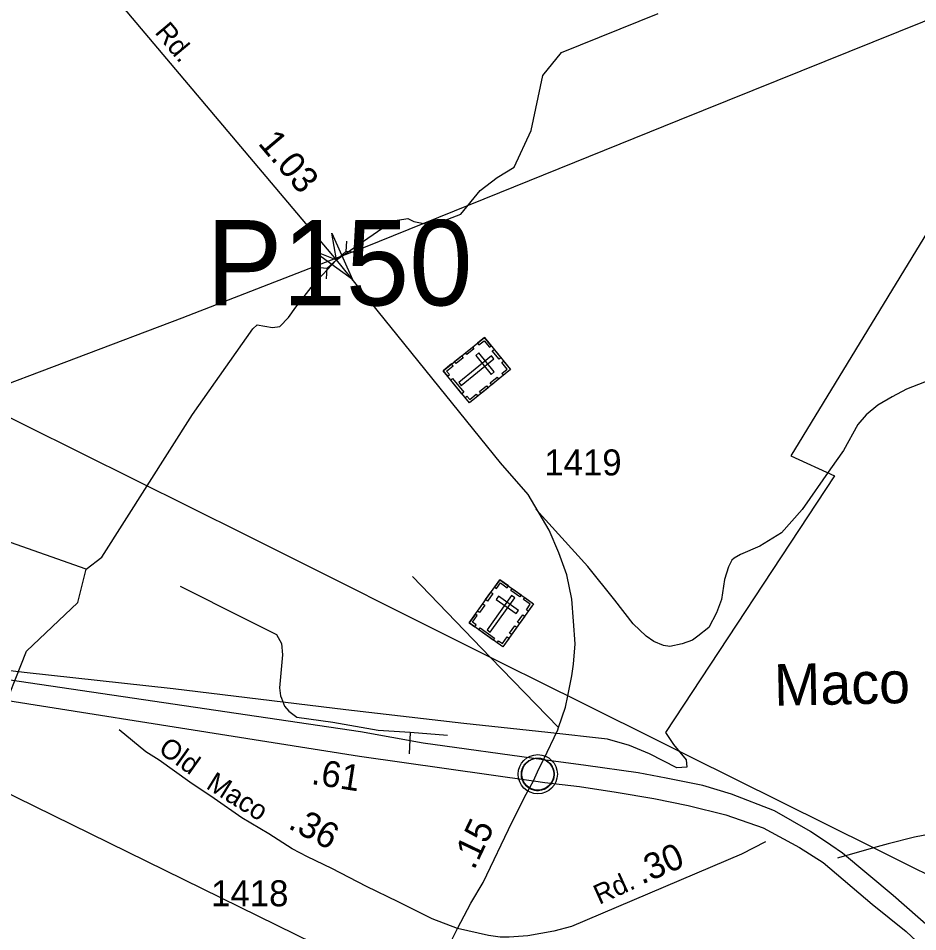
# Model space of a CAD drawing. Extents: x 2225501 to 2309677, y 165449 to 227696.
# Drawn here: x 2257649 to 2261977, y 195485 to 199877 of the extents above; entities that cross this region are included whole.
import ezdxf

# ---------------------------------------------------------------- set-up
doc = ezdxf.new("R2010")
doc.units = 0
for name, color, linetype in [('Black Area Fill Shapes', 7, 'Continuous'), ('E_RDY_CMT_EOP', 7, 'Continuous'), ('ENG SEALS CELL', 7, 'Continuous'), ('MARK ENDS WORD SYMBOL CELL', 7, 'Continuous'), ('Old_Level_3', 7, 'Continuous'), ('Old_Level_33', 7, 'Continuous'), ('Old_Level_44', 7, 'Continuous'), ('Old_Level_46', 7, 'Continuous'), ('Old_Level_50', 7, 'Continuous'), ('Old_Level_52', 7, 'Continuous'), ('P_HYD_Diversion_Ditch_Label', 7, 'Continuous'), ('P_HYD_Drop_Inlet_Grate_3_Narrow_Slot_and_Sag_Grates_840_22_Type_A_60_Dia-Top_CELL', 7, 'Continuous'), ('P_HYD_Endwall_838_01_48_Dia_Single_CELL', 7, 'Continuous'), ('P_HYD_RipRap_Pad_876_02_36in_Outlet_With_Ditch-Top_CELL', 7, 'Continuous'), ('P_RDY_Dimension_Text', 7, 'Continuous'), ('Prop Mkg Solid Yellow Edge Line', 7, 'Continuous'), ('Prop Support', 7, 'Continuous'), ('Raster_Level_0', 7, 'Continuous'), ('Scratch_Level_4', 7, 'Continuous'), ('Typical Terminator CELL', 7, 'Continuous')]:
    doc.layers.add(name, color=color, linetype=linetype)

msp = doc.modelspace()

# ---------------------------------------------------------------- linework, layer by layer
at = {"layer": 'Black Area Fill Shapes'}
for p, q in [((2260818.3, 196358.1), (2260293.7, 196618.7)), ((2260878.5, 196328.2), (2260818.3, 196358.1)), ((2261764.5, 195887.9), (2260878.5, 196328.2))]:
    msp.add_line(p, q, dxfattribs=at)
for points in [[(2262843.4, 200184.7), (2262114.8, 199904.5), (2260829.4, 199388.1), (2259311, 198774), (2259154.8, 198713.5)], [(2259154.8, 198713.5), (2258436.2, 198435), (2257417.6, 198050.9)], [(2259922.2, 196804.3), (2258742.4, 197393.8), (2257417.6, 198050.9)], [(2260293.7, 196618.7), (2260237.9, 196646.5), (2259922.2, 196804.3)], [(2264419.4, 194543.5), (2262221.2, 195661.1), (2261764.5, 195887.9)]]:
    msp.add_lwpolyline(points, dxfattribs=at)
at = {"layer": 'ENG SEALS CELL'}
msp.add_lwpolyline([(2259158.2, 198843.7), (2259257.2, 198620.8), (2259060.1, 198764.3), (2259180.6, 198715.6)], close=True, dxfattribs=at)
at = {"layer": 'Old_Level_3'}
for p, q in [((2259922.2, 196804.3), (2259545.7, 197192.6)), ((2260249.4, 196466.7), (2259922.2, 196804.3)), ((2259535.6, 196444.5), (2259533.7, 196408.1)), ((2259535.6, 196444.5), (2259714.6, 196430)), ((2259533.7, 196408.1), (2259530.1, 196340.4)), ((2259308.7, 195312.8), (2257312.8, 196291)), ((2261669.9, 195861.5), (2261600, 195841.9)), ((2261764.5, 195887.9), (2261669.9, 195861.5)), ((2261600, 195841.9), (2261591, 195839.4))]:
    msp.add_line(p, q, dxfattribs=at)
for points in [[(2263428.3, 199760.2), (2263330.4, 199632.5), (2263077.1, 199318.5), (2262950.9, 199099.6), (2262856, 198960.9), (2262781.6, 198776.4), (2262724.3, 198690), (2262583.6, 198528.9), (2262379.3, 198345.4), (2262276, 198256.4), (2262075, 198152.9), (2261923.5, 198093.7), (2261853.8, 198057.1), (2261784.2, 198016.6), (2261728.5, 197970.1), (2261689, 197923.7), (2261620, 197799.3), (2261557.7, 197710.9)], [(2261557.7, 197710.9), (2261420.3, 197515.8), (2261321.4, 197403), (2261217.9, 197338.2), (2261124.4, 197299.5), (2261094.4, 197281.2), (2261082.4, 197271.1), (2261066.8, 197239), (2261047.3, 197178.8), (2261032.2, 197082.7), (2261008.5, 197018.6), (2260971.2, 196948.3), (2260919.6, 196905.9), (2260893.8, 196887.6), (2260843.9, 196869.2), (2260784, 196856.8), (2260753.9, 196860.6), (2260707.9, 196880.3), (2260669.6, 196905.8), (2260607.2, 196965.4), (2260520.4, 197078.7), (2260389, 197241.4), (2260138.9, 197517.2)], [(2258428.2, 197146), (2258737.7, 196991.2), (2258892.4, 196913.8), (2258916.6, 196870.3), (2258921.5, 196817), (2258911.8, 196710.6), (2258906.9, 196657.4), (2258911.8, 196618.7), (2258915.9, 196608.3)], [(2264213.9, 196708.8), (2264138.5, 196626.3), (2264122.6, 196618.2), (2264068.8, 196599.8), (2264032.8, 196599.5), (2263983, 196589.1), (2263955, 196588.9), (2263893.1, 196580.3), (2263837.3, 196552), (2263785.6, 196511.4), (2263350.9, 196124.1), (2263301.3, 196089.7), (2263277.4, 196067.6), (2263231.7, 196037.1), (2263199.9, 196020.9), (2263098, 196002.1), (2262894.3, 195982.5), (2262476.4, 195985), (2262344.6, 195990), (2262174.7, 195976.5), (2262044.9, 195955.4), (2261961, 195938.9), (2261835.3, 195907.7), (2261764.5, 195887.9)], [(2258915.9, 196608.3), (2258931.1, 196570.3), (2258950.5, 196546.1), (2258989.2, 196517.1), (2259163.3, 196492.9), (2259380.9, 196454.2), (2259535.6, 196444.5)]]:
    msp.add_lwpolyline(points, dxfattribs=at)
at = {"layer": 'Old_Level_33'}
for points in [[(2260176.7, 196311.4), (2260245.5, 196456.5), (2260249.4, 196466.7), (2260282.7, 196564.8), (2260293.7, 196618.7), (2260313.4, 196715), (2260320.9, 196771), (2260328.2, 196869.1), (2260321.1, 196979), (2260313.2, 197083.4), (2260289.4, 197200.9), (2260250.2, 197306.6), (2260204.2, 197415.6), (2260102.1, 197587.7), (2259969.3, 197739.9), (2259180.6, 198715.6), (2257441.8, 200774), (2257406.3, 200835.2)], [(2259763.1, 195500.3), (2259640.9, 195547.4), (2259476.5, 195629.2), (2259324.2, 195701.9), (2259157.5, 195788.6), (2259040.4, 195845), (2258967.9, 195884.1), (2258854.3, 195956), (2258725.6, 196032.9), (2258592.8, 196125.9), (2258474.4, 196204.8), (2258327.5, 196309.6), (2258262.5, 196349.9), (2258134.9, 196456.2)], [(2261244.4, 195917), (2261128.6, 195857.3), (2260311.7, 195510.7), (2260226.7, 195487.1), (2260101.7, 195465.8), (2260011.4, 195458.2), (2259967.8, 195458.6), (2259911.7, 195466.3), (2259763.1, 195500.3)]]:
    msp.add_lwpolyline(points, dxfattribs=at)
at = {"layer": 'Old_Level_44'}
for p, q in [((2259228.2, 198806.1), (2259226.1, 198755.4)), ((2259135, 198675.9), (2259226.1, 198755.4)), ((2259276.7, 198750.6), (2259226.1, 198755.4)), ((2259084.5, 198680.7), (2259135, 198675.9)), ((2259133, 198625.1), (2259135, 198675.9))]:
    msp.add_line(p, q, dxfattribs=at)
at = {"layer": 'Old_Level_46'}
for points in [[(2260176.7, 196311.4), (2259597.7, 196392.1), (2259295.9, 196446.1), (2256956.7, 196790)], [(2256960.1, 196697.4), (2259291.8, 196328.6), (2260129, 196210.1)], [(2264217.6, 193561.9), (2264055, 193704.6), (2263946.8, 193788.4), (2263787.2, 193926.8), (2263500, 194184.9), (2263249.2, 194403.1), (2263105.6, 194549.5), (2262415.7, 195153.5), (2262043.4, 195496.8), (2261859.5, 195658.7), (2261615.3, 195862.4), (2261558.7, 195901.5), (2261461.5, 195966.3), (2261288.3, 196066.6), (2261080.3, 196146.7), (2260942.6, 196188.6), (2260766.4, 196223.2), (2260631.5, 196248.5), (2260380.2, 196284.4), (2260176.7, 196311.4)], [(2260129, 196210.1), (2260182.5, 196202.5), (2260349.2, 196183.2), (2260525.3, 196155.2), (2260707.8, 196126.2), (2260872.5, 196091.5), (2261053.4, 196046.8), (2261232.8, 195983.9), (2261407.6, 195889.4), (2261522.3, 195817.9), (2261757.7, 195618.2), (2261921.5, 195486), (2262216.4, 195210.8), (2262990.7, 194529), (2263196.2, 194348.8), (2263442, 194122.8), (2263721, 193886.9), (2263872.7, 193751), (2263970.5, 193659.8), (2264144.9, 193502.9)]]:
    msp.add_lwpolyline(points, dxfattribs=at)
at = {"layer": 'Old_Level_50'}
for points in [[(2260129, 196210.1), (2260154.7, 196268.2), (2260176.7, 196311.4)], [(2259763.1, 195500.3), (2259826.1, 195622.5), (2259886.6, 195722.2), (2260025.5, 196013.6), (2260093.6, 196146.1), (2260129, 196210.1)], [(2258595.8, 192338.5), (2258629.6, 192532.4), (2258664.3, 192655.9), (2258691.3, 192729.2), (2258737.6, 192818.2), (2258791.6, 192928.2), (2258843.7, 193034.3), (2258916, 193180), (2258987.4, 193322.8), (2259027.9, 193421.3), (2259081.9, 193556.3), (2259101.2, 193637.4), (2259145.6, 193859.3), (2259184.1, 194038.8), (2259210.2, 194167.1), (2259233.7, 194275.2), (2259281.8, 194509.4), (2259328.8, 194619.8), (2259446.5, 194872.8), (2259510.1, 195004.1), (2259562.2, 195102.5), (2259660.6, 195295.4), (2259763.1, 195500.3)]]:
    msp.add_lwpolyline(points, dxfattribs=at)
at = {"layer": 'P_HYD_Diversion_Ditch_Label'}
msp.add_lwpolyline([(2260071.4, 196254.6), (2260072.4, 196260.2), (2260074.2, 196266.8), (2260077.1, 196274), (2260080, 196279.7), (2260083.4, 196285.4), (2260087.1, 196290.6), (2260091.1, 196294.9), (2260095.7, 196299.5), (2260101.2, 196304.1), (2260106.6, 196307.8), (2260111.5, 196310.6), (2260116.6, 196313.1), (2260122, 196315.4), (2260127.7, 196317.2), (2260132, 196318.4), (2260136.8, 196319.1), (2260141, 196319.8), (2260147.3, 196320.1), (2260151.8, 196320), (2260157.4, 196319.7), (2260162.3, 196319), (2260167.2, 196318), (2260172.2, 196316.6), (2260177.4, 196314.7), (2260184.1, 196311.7), (2260190.3, 196308.2), (2260195.4, 196304.7), (2260200.5, 196300.7), (2260203.9, 196297.5), (2260208, 196293.2), (2260211.8, 196288.5), (2260214.9, 196283.9), (2260218.1, 196278.9), (2260220.5, 196273.7), (2260222.5, 196268.7), (2260224.1, 196263.7), (2260225.4, 196259.1), (2260226.5, 196253), (2260227.1, 196248.3), (2260227.4, 196242.3), (2260227.2, 196236.5), (2260226.6, 196230.9), (2260225.7, 196225.4), (2260224, 196219.2), (2260222.1, 196213.4), (2260219.9, 196208.3), (2260216.7, 196202.3), (2260213.4, 196197), (2260210, 196192.3), (2260205.7, 196187.6), (2260200.4, 196182.6), (2260195.4, 196178.5), (2260190.4, 196175), (2260186.1, 196172.5), (2260179.3, 196169.3), (2260172.1, 196166.6), (2260166.2, 196165.1), (2260159.6, 196163.8), (2260155.1, 196163.3), (2260150.7, 196163.1), (2260145.1, 196163.1), (2260140.8, 196163.5), (2260135.2, 196164.2), (2260129.2, 196165.5), (2260124.7, 196166.8), (2260119.5, 196168.7), (2260114.9, 196170.7), (2260111, 196172.9), (2260104.2, 196177), (2260098.6, 196181.3), (2260093.7, 196185.8), (2260089.2, 196190.6), (2260086, 196194.6), (2260083.1, 196198.8), (2260079, 196205.9), (2260077.2, 196209.4), (2260075.5, 196213.4), (2260072.9, 196221.6), (2260071.4, 196228.7), (2260070.7, 196233.8), (2260070.4, 196240.2), (2260070.3, 196244.8), (2260070.9, 196251.3)], close=True, dxfattribs=at)
for centre, radius in [((2260149, 196242.2), 94.3), ((2260148.7, 196242.5), 76.7)]:
    msp.add_circle(centre, radius, dxfattribs=at)
at = {"layer": 'P_HYD_Endwall_838_01_48_Dia_Single_CELL'}
msp.add_lwpolyline([(2262842.5, 200192.5), (2261366.2, 197772.7), (2261577, 197677.7), (2260763, 196442.2), (2260802.2, 196384.7), (2260862.2, 196311.2), (2260865.8, 196276.6), (2260817.5, 196273.6), (2260687.2, 196340.6), (2260589.5, 196380.7), (2260484.8, 196410.3), (2260197, 196442.9), (2259793.2, 196485.6), (2259224.8, 196551.9), (2258394, 196652.1), (2257678.2, 196731.8), (2257280, 196779.1), (2256995.8, 196809.4), (2256790.2, 196891.6), (2256494.5, 197038.7)], dxfattribs=at)
at = {"layer": 'P_HYD_RipRap_Pad_876_02_36in_Outlet_With_Ditch-Top_CELL'}
msp.add_lwpolyline([(2262842.5, 200192.5), (2261366.2, 197772.7), (2261577, 197677.7), (2260763, 196442.2), (2260802.2, 196384.7), (2260862.2, 196311.2), (2260865.8, 196276.6), (2260817.5, 196273.6), (2260687.2, 196340.6), (2260589.5, 196380.7), (2260484.8, 196410.3), (2260197, 196442.9), (2259793.2, 196485.6), (2259224.8, 196551.9), (2258394, 196652.1), (2257678.2, 196731.8), (2257280, 196779.1), (2256995.8, 196809.4), (2256790.2, 196891.6), (2256494.5, 197038.7)], dxfattribs=at)
at = {"layer": 'Prop Mkg Solid Yellow Edge Line'}
for points in [[(2259891.9, 198342.8), (2260017.4, 198188.3), (2259819.8, 198027.7), (2259694.3, 198182.3)], [(2259858.3, 198315.5), (2259865.4, 198306.7), (2259890.4, 198327), (2259916, 198295.5), (2259924.6, 198302.5), (2259891.9, 198342.8)], [(2259800.7, 198268.8), (2259834.3, 198296.1), (2259841.5, 198287.2), (2259807.9, 198259.9)], [(2259938.6, 198285.3), (2259971.3, 198245.1), (2259962.4, 198237.9), (2259929.7, 198278.1)], [(2259748.5, 198226.4), (2259782.1, 198253.7), (2259789.3, 198244.9), (2259755.7, 198217.6)], [(2259937.9, 198239.7), (2259926.1, 198254.2), (2259768.7, 198126.4), (2259780.5, 198111.9)], [(2259864.8, 198268.2), (2259850.3, 198256.4), (2259924.5, 198165.1), (2259939, 198176.8)], [(2259715.1, 198156.6), (2259724.1, 198163.9), (2259710.2, 198180.9), (2259741.6, 198206.4), (2259734.5, 198215.1), (2259694.3, 198182.3)], [(2259983.8, 198160.9), (2259976.6, 198169.7), (2260001.6, 198190), (2259976.1, 198221.5), (2259984.7, 198228.5), (2260017.4, 198188.2)], [(2259739.4, 198144.9), (2259792.9, 198079), (2259784, 198071.9), (2259730.5, 198137.7)], [(2259919.9, 198123.7), (2259953.5, 198151), (2259960.7, 198142.1), (2259927.1, 198114.8)], [(2259868.7, 198082.1), (2259902.3, 198109.4), (2259909.5, 198100.6), (2259875.9, 198073.3)], [(2259798.9, 198053.5), (2259807.8, 198060.7), (2259821.7, 198043.6), (2259853, 198069.1), (2259860.1, 198060.5), (2259819.8, 198027.7)], [(2259966, 197177.6), (2260128.4, 197062.3), (2259981, 196854.7), (2259818.7, 196969.9)], [(2259941, 197142.2), (2259950.2, 197135.7), (2259968.8, 197161.9), (2260001.9, 197138.4), (2260008.4, 197147.5), (2259966, 197177.6)], [(2260026.4, 197134.7), (2260068.7, 197104.7), (2260062.1, 197095.4), (2260019.8, 197125.4)], [(2259898, 197081.8), (2259923.1, 197117.1), (2259932.4, 197110.5), (2259907.3, 197075.2)], [(2260038, 197090.6), (2260022.7, 197101.4), (2259905.4, 196936), (2259920.6, 196925.2)], [(2259959.9, 197098.4), (2259949.1, 197083.2), (2260045.1, 197015.1), (2260055.9, 197030.3)], [(2260103.3, 197026.9), (2260094.1, 197033.5), (2260112.7, 197059.7), (2260079.6, 197083.2), (2260086.1, 197092.3), (2260128.4, 197062.3)], [(2259859.1, 197027), (2259884.2, 197062.3), (2259893.5, 197055.7), (2259868.4, 197020.4)], [(2259845.7, 196950.8), (2259852.3, 196960.2), (2259834.4, 196972.9), (2259857.8, 197005.9), (2259848.7, 197012.3), (2259818.6, 196970)], [(2260051.7, 196973.9), (2260076.8, 197009.3), (2260086.1, 197002.7), (2260061, 196967.4)], [(2259872.2, 196946), (2259941.4, 196896.9), (2259934.8, 196887.6), (2259865.6, 196936.7)], [(2260013.6, 196920.2), (2260038.6, 196955.5), (2260047.9, 196948.9), (2260022.8, 196913.6)], [(2259954, 196873.9), (2259960.6, 196883.2), (2259978.6, 196870.5), (2260002, 196903.5), (2260011, 196897), (2259981, 196854.7)]]:
    msp.add_lwpolyline(points, close=True, dxfattribs=at)
at = {"layer": 'Prop Support'}
msp.add_lwpolyline([(2257976.7, 197228), (2257584.7, 197366.8), (2257283.7, 197431.8), (2256982.6, 197562.3), (2256580.7, 197793.2), (2256244.7, 198222.8), (2256076.7, 198360.5), (2255901.6, 198426.3), (2255659.7, 198424.5), (2255501.8, 198375), (2255013.7, 198004.1), (2254579.6, 198042), (2254396.7, 198006.2), (2254148.6, 197755.2), (2254040.6, 197763.9), (2251865.6, 198918.2), (2251519.7, 199088.4)], dxfattribs=at)
at = {"layer": 'Typical Terminator CELL'}
for points in [[(2257976.7, 197228), (2258051.8, 197285.6), (2258487.7, 197972.5), (2258777.4, 198383.8), (2258798.9, 198402.9), (2258872.8, 198391), (2258908.6, 198395.8), (2258949.2, 198438.7), (2258984.9, 198488.9), (2259069.6, 198597.5), (2259180.6, 198715.6), (2259398.9, 198867.2), (2259474, 198906.6), (2259524.1, 198913.8), (2259552.7, 198899.4), (2259641, 198882.7), (2259778.7, 198934.6), (2259872.4, 199049.8), (2259953.5, 199111.9), (2260034.6, 199162), (2260116.7, 199338.1), (2260172.6, 199602.6), (2260263.7, 199712.4), (2260728.7, 199900.1)], [(2257554.7, 196498.2), (2257688.6, 196833.4), (2257936.8, 197068.1), (2257976.7, 197228)]]:
    msp.add_lwpolyline(points, dxfattribs=at)

# ---------------------------------------------------------------- texts
at = {"layer": 'E_RDY_CMT_EOP'}
for s, p in [('1419', (2260180.4, 197679.1)), ('1418', (2258577.4, 195607.2))]:
    msp.add_text(s, height=125, dxfattribs=at).set_placement(p)
at = {"layer": 'MARK ENDS WORD SYMBOL CELL'}
for s, rotation, p in [('Rd.', 309.9122, (2258302.8, 199808.7)), ('Old', 324.489, (2258318.5, 196350.2)), ('Maco', 328.1011, (2258548.1, 196177.4)), ('Rd.', 24.4276, (2260444.6, 195613.9))]:
    msp.add_text(s, height=95, rotation=rotation, dxfattribs=at).set_placement(p)
at = {"layer": 'Old_Level_52'}
msp.add_text('P150', height=410.1, dxfattribs=at).set_placement((2258554.5, 198496.6))
at = {"layer": 'P_HYD_Drop_Inlet_Grate_3_Narrow_Slot_and_Sag_Grates_840_22_Type_A_60_Dia-Top_CELL'}
msp.add_text('Maco', height=200, rotation=1.2211, dxfattribs=at).set_placement((2261287.5, 196570.9))
at = {"layer": 'P_RDY_Dimension_Text'}
for s, rotation, p in [('1.03', 310.1894, (2258799.2, 199274.4)), ('.36', 332.0007, (2258942.7, 195985)), ('.30', 22.9931, (2260649.3, 195710.9))]:
    msp.add_text(s, height=125, rotation=rotation, dxfattribs=at).set_placement(p)
at = {"layer": 'Raster_Level_0'}
msp.add_text('.61', height=125, rotation=351.0127, dxfattribs=at).set_placement((2259055, 196195.8))
at = {"layer": 'Scratch_Level_4'}
msp.add_text('.15', height=125, rotation=64.5172, dxfattribs=at).set_placement((2259842.1, 195778))

doc.saveas('drawing.dxf')
